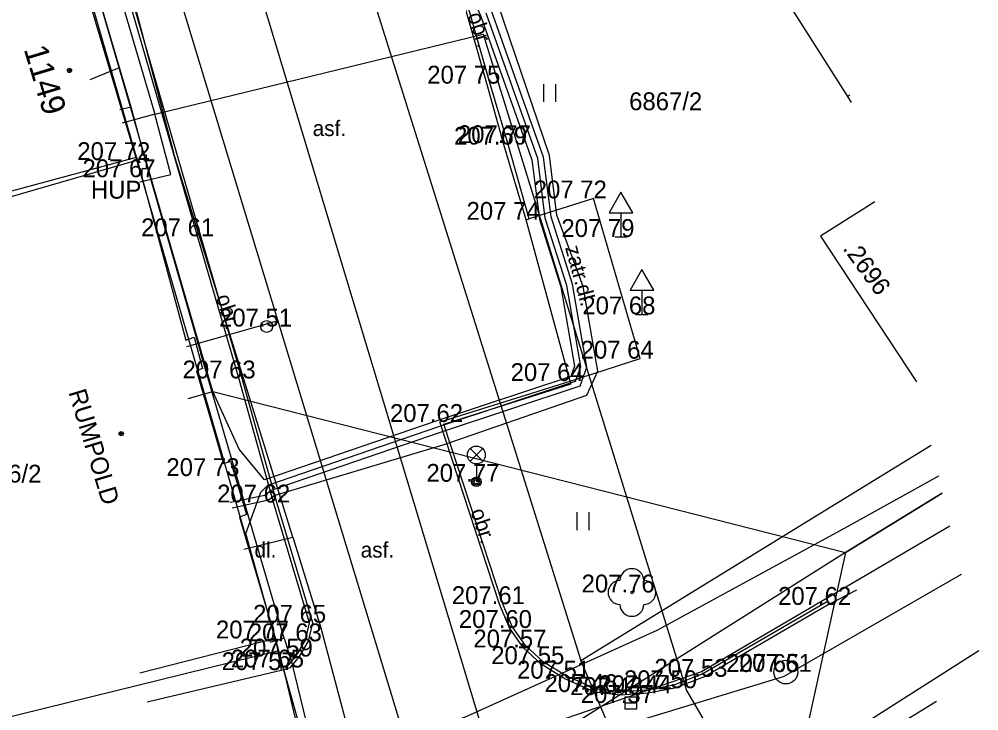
# Model space of a CAD drawing. Extents: x -524633 to -524336, y -1187893 to -1187683.
# Drawn here: x -524505.26 to -524464.98, y -1187849.14 to -1187820.09 of the extents above; entities that cross this region are included whole.
import ezdxf

# ---------------------------------------------------------------- set-up
doc = ezdxf.new("R2010")
doc.units = 0
for name, color, linetype in [('Hranice parcel', 7, 'Continuous'), ('Parcelní čísla', 7, 'Continuous'), ('Vrstva 1', 7, 'Continuous'), ('Vrstva 10', 7, 'Continuous'), ('Vrstva 11', 7, 'Continuous'), ('Vrstva 22', 7, 'Continuous'), ('Vrstva 24', 7, 'Continuous'), ('Vrstva 27', 7, 'Continuous'), ('Vrstva 28', 7, 'Continuous'), ('Vrstva 3', 7, 'Continuous'), ('Vrstva 33', 7, 'Continuous'), ('Vrstva 34', 7, 'Continuous'), ('Vrstva 36', 7, 'Continuous'), ('Vrstva 39', 7, 'Continuous'), ('Vrstva 4', 7, 'Continuous'), ('Vrstva 40', 7, 'Continuous'), ('Vrstva 41', 7, 'Continuous'), ('Vrstva 47', 7, 'Continuous'), ('Vrstva 5', 7, 'Continuous'), ('Vrstva 52', 7, 'Continuous'), ('Vrstva 53', 7, 'Continuous'), ('Vrstva 54', 7, 'Continuous'), ('Vrstva 55', 7, 'Continuous'), ('Vrstva 56', 7, 'Continuous'), ('Vrstva 58', 7, 'Continuous'), ('Vrstva 7', 7, 'Continuous')]:
    doc.layers.add(name, color=color, linetype=linetype)

msp = doc.modelspace()

# ---------------------------------------------------------------- linework, layer by layer
at = {"layer": 'Hranice parcel'}
for p, q in [((-524500.33, -1187825.89), (-524502.57, -1187818.16)), ((-524470.48, -1187823.34), (-524473.64, -1187818.37)), ((-524470.389, -1187823.283), (-524470.48, -1187823.34)), ((-524470.317, -1187823.593), (-524470.48, -1187823.34)), ((-524494.54, -1187845.97), (-524494.37, -1187846.6)), ((-524477.11, -1187857.62), (-524481.69, -1187847.02))]:
    msp.add_line(p, q, dxfattribs=at)
for points in [[(-524490.45, -1187819.04), (-524486.12, -1187832.88), (-524481.69, -1187847.02)], [(-524515.16, -1187829.92), (-524513.47, -1187829.44), (-524512.21, -1187829.1), (-524500.33, -1187825.89)], [(-524500.33, -1187825.89), (-524498.27, -1187833.57), (-524497.91, -1187833.45), (-524497.56, -1187834.77), (-524497.81, -1187834.86), (-524496.68, -1187838.75), (-524496.39, -1187838.65), (-524495.72, -1187840.9), (-524496.01, -1187841.01), (-524494.54, -1187845.97)], [(-524469.349, -1187827.764), (-524471.63, -1187829.2), (-524467.598, -1187835.318)], [(-524515.16, -1187829.92), (-524509.15, -1187850.24), (-524494.37, -1187846.6)], [(-524481.69, -1187847.02), (-524471.22, -1187840.59), (-524466.981, -1187837.979)], [(-524494.37, -1187846.6), (-524494.12, -1187847.57), (-524492.85, -1187852.95), (-524492.64, -1187853.18)]]:
    msp.add_lwpolyline(points, dxfattribs=at)
at = {"layer": 'Vrstva 1'}
for p, q in [((-524485.63, -1187822.8), (-524485.63, -1187822.8)), ((-524484.91, -1187825.36), (-524484.91, -1187825.36)), ((-524484.75, -1187825.3), (-524484.75, -1187825.3)), ((-524500.32, -1187826.01), (-524500.32, -1187826.01)), ((-524500.1, -1187826.73), (-524500.1, -1187826.73)), ((-524481.16, -1187827.62), (-524481.16, -1187827.62)), ((-524483.98, -1187828.52), (-524483.98, -1187828.52)), ((-524497.64, -1187829.21), (-524497.64, -1187829.21)), ((-524480, -1187829.24), (-524480, -1187829.24)), ((-524479.12, -1187832.49), (-524479.12, -1187832.49)), ((-524494.87, -1187833), (-524494.87, -1187833)), ((-524479.19, -1187834.35), (-524479.19, -1187834.35)), ((-524495.9, -1187835.18), (-524495.9, -1187835.18)), ((-524482.13, -1187835.29), (-524482.13, -1187835.29)), ((-524487.6, -1187837.01), (-524487.6, -1187837.01)), ((-524496.58, -1187839.28), (-524496.58, -1187839.28)), ((-524486.07, -1187839.52), (-524486.07, -1187839.52)), ((-524494.45, -1187840.39), (-524494.45, -1187840.39)), ((-524479.54, -1187844.17), (-524479.54, -1187844.17)), ((-524485.1, -1187844.66), (-524485.1, -1187844.66)), ((-524471.31, -1187844.69), (-524471.31, -1187844.69)), ((-524492.94, -1187845.44), (-524492.94, -1187845.44)), ((-524484.68, -1187845.66), (-524484.68, -1187845.66)), ((-524494.5, -1187846.1), (-524494.5, -1187846.1)), ((-524493.12, -1187846.22), (-524493.12, -1187846.22)), ((-524484.1, -1187846.48), (-524484.1, -1187846.48)), ((-524493.5, -1187846.86), (-524493.5, -1187846.86)), ((-524483.35, -1187847.18), (-524483.35, -1187847.18)), ((-524494.26, -1187847.43), (-524494.26, -1187847.43)), ((-524493.87, -1187847.32), (-524493.87, -1187847.32)), ((-524473.08, -1187847.51), (-524473.08, -1187847.51)), ((-524473.05, -1187847.5), (-524473.05, -1187847.5)), ((-524482.36, -1187847.79), (-524482.36, -1187847.79)), ((-524476.5, -1187847.71), (-524476.5, -1187847.71)), ((-524481.1, -1187848.35), (-524481.1, -1187848.35)), ((-524480.04, -1187848.48), (-524480.04, -1187848.48)), ((-524478.85, -1187848.4), (-524478.85, -1187848.4)), ((-524477.75, -1187848.19), (-524477.75, -1187848.19)), ((-524479.59, -1187848.81), (-524479.59, -1187848.81))]:
    msp.add_line(p, q, dxfattribs=at)
at = {"layer": 'Vrstva 10'}
for p, q in [((-524470.108, -1187844.07), (-524471.309, -1187844.69)), ((-524499.889, -1187848.761), (-524494.259, -1187847.43))]:
    msp.add_line(p, q, dxfattribs=at)
for points in [[(-524485.629, -1187822.8), (-524486.979, -1187818.07), (-524488.219, -1187813.67)], [(-524497.64, -1187829.21), (-524500.549, -1187819.15)], [(-524483.979, -1187828.52), (-524484.909, -1187825.36), (-524485.629, -1187822.8)], [(-524482.129, -1187835.29), (-524483.979, -1187828.52)], [(-524495.899, -1187835.18), (-524497.64, -1187829.21)], [(-524494.449, -1187840.39), (-524495.899, -1187835.18)], [(-524487.589, -1187837.01), (-524482.129, -1187835.29)], [(-524471.309, -1187844.69), (-524476.499, -1187847.71), (-524477.749, -1187848.19), (-524478.849, -1187848.4), (-524480.039, -1187848.48), (-524481.1, -1187848.35), (-524482.36, -1187847.79), (-524483.349, -1187847.18), (-524484.099, -1187846.48), (-524484.679, -1187845.66), (-524485.1, -1187844.66), (-524487.6, -1187837.01)], [(-524492.939, -1187845.44), (-524494.449, -1187840.39)], [(-524494.259, -1187847.43), (-524493.869, -1187847.32), (-524493.499, -1187846.86), (-524493.119, -1187846.22), (-524492.939, -1187845.44)], [(-524466.75, -1187848.751), (-524468.76, -1187849.98)]]:
    msp.add_lwpolyline(points, dxfattribs=at)
at = {"layer": 'Vrstva 11'}
for p, q in [((-524497.765, -1187829.246), (-524500.674, -1187819.186)), ((-524481.159, -1187827.62), (-524483.855, -1187828.48)), ((-524496.024, -1187835.216), (-524497.765, -1187829.246)), ((-524494.574, -1187840.426), (-524496.024, -1187835.216)), ((-524493.073, -1187845.444), (-524494.574, -1187840.426))]:
    msp.add_line(p, q, dxfattribs=at)
for points in [[(-524485.504, -1187822.764), (-524486.864, -1187818), (-524486.979, -1187818.07)], [(-524483.979, -1187828.52), (-524483.855, -1187828.48), (-524484.749, -1187825.3), (-524485.504, -1187822.764)], [(-524479.189, -1187834.35), (-524481.159, -1187827.62)], [(-524482.129, -1187835.29), (-524479.189, -1187834.35)], [(-524487.435, -1187837.098), (-524482.09, -1187835.414), (-524482.129, -1187835.29)], [(-524471.375, -1187844.578), (-524476.556, -1187847.592), (-524477.785, -1187848.064), (-524478.866, -1187848.271), (-524480.036, -1187848.349), (-524481.065, -1187848.223), (-524482.299, -1187847.675), (-524483.27, -1187847.076), (-524484.001, -1187846.394), (-524484.565, -1187845.597), (-524484.978, -1187844.615), (-524487.435, -1187837.098)], [(-524494.282, -1187847.301), (-524493.944, -1187847.206), (-524493.606, -1187846.786), (-524493.241, -1187846.171), (-524493.073, -1187845.444)]]:
    msp.add_lwpolyline(points, dxfattribs=at)
at = {"layer": 'Vrstva 22'}
msp.add_circle((-524479.54, -1187844.17), 0.05, dxfattribs=at)
for centre, start, end in [((-524479.54, -1187843.67), 0, 180), ((-524480.04, -1187844.17), 90, 270), ((-524479.04, -1187844.17), 270, 90), ((-524479.54, -1187844.67), 180, 0)]:
    msp.add_arc(centre, 0.5, start, end, dxfattribs=at)
at = {"layer": 'Vrstva 24'}
for p, q in [((-524500.099, -1187825.809), (-524500.099, -1187825.441)), ((-524499.916, -1187825.811), (-524500.099, -1187825.809)), ((-524499.916, -1187826.363), (-524499.916, -1187825.811)), ((-524500.099, -1187826.73), (-524500.099, -1187826.363)), ((-524500.099, -1187826.363), (-524499.916, -1187826.363))]:
    msp.add_line(p, q, dxfattribs=at)
at = {"layer": 'Vrstva 27'}
msp.add_line((-524479.84, -1187848.81), (-524479.34, -1187848.81), dxfattribs=at)
msp.add_lwpolyline([(-524479.84, -1187849.06), (-524479.34, -1187849.06), (-524479.34, -1187848.56), (-524479.84, -1187848.56)], close=True, dxfattribs=at)
msp.add_circle((-524473.08, -1187847.51), 0.5, dxfattribs=at)
at = {"layer": 'Vrstva 28'}
msp.add_circle((-524494.87, -1187833), 0.25, dxfattribs=at)
at = {"layer": 'Vrstva 33'}
for p, q in [((-524486.334, -1187838.66), (-524485.804, -1187838.13)), ((-524486.334, -1187838.13), (-524485.804, -1187838.66)), ((-524486.069, -1187838.77), (-524486.069, -1187839.52))]:
    msp.add_line(p, q, dxfattribs=at)
for centre, radius in [((-524486.069, -1187838.395), 0.375), ((-524486.069, -1187839.52), 0.2), ((-524486.069, -1187839.52), 0.145), ((-524486.069, -1187839.52), 0.0876)]:
    msp.add_circle(centre, radius, dxfattribs=at)
at = {"layer": 'Vrstva 34'}
for p, q in [((-524479.999, -1187828.224), (-524479.999, -1187829.24)), ((-524480.249, -1187829.24), (-524479.749, -1187829.24)), ((-524479.119, -1187831.474), (-524479.119, -1187832.49)), ((-524479.369, -1187832.49), (-524478.869, -1187832.49))]:
    msp.add_line(p, q, dxfattribs=at)
for points in [[(-524480.499, -1187828.224), (-524479.499, -1187828.224), (-524479.999, -1187827.356)], [(-524479.619, -1187831.474), (-524478.619, -1187831.474), (-524479.119, -1187830.606)]]:
    msp.add_lwpolyline(points, close=True, dxfattribs=at)
at = {"layer": 'Vrstva 36'}
for p, q in [((-524483.236, -1187823.568), (-524483.236, -1187822.818)), ((-524482.735, -1187823.568), (-524482.735, -1187822.818)), ((-524481.838, -1187841.548), (-524481.838, -1187840.798)), ((-524481.337, -1187841.548), (-524481.337, -1187840.798))]:
    msp.add_line(p, q, dxfattribs=at)
at = {"layer": 'Vrstva 39'}
for centre, radius in [((-524503.147, -1187822.243), 0.09), ((-524503.147, -1187822.243), 0.0398), ((-524500.973, -1187837.5), 0.09), ((-524500.973, -1187837.5), 0.0398)]:
    msp.add_circle(centre, radius, dxfattribs=at)
at = {"layer": 'Vrstva 5'}
for p, q in [((-524500.319, -1187826.01), (-524502.239, -1187819.58)), ((-524509.062, -1187828.548), (-524500.319, -1187826.01)), ((-524494.499, -1187846.1), (-524500.319, -1187826.01)), ((-524494.499, -1187846.1), (-524500.201, -1187847.552))]:
    msp.add_line(p, q, dxfattribs=at)
at = {"layer": 'Vrstva 52'}
for points in [[(-524496.398, -1187840.378), (-524494.948, -1187840.08), (-524494.688, -1187839.875), (-524487.612, -1187837.45), (-524481.715, -1187835.492), (-524481.43, -1187834.708), (-524482.034, -1187831.222), (-524482.934, -1187828.39), (-524483.247, -1187825.883), (-524485.431, -1187819.747), (-524488.09, -1187813.944), (-524489.77, -1187814.215), (-524492.275, -1187815.202), (-524493.527, -1187813.248), (-524494.448, -1187809.538), (-524497.926, -1187800.125), (-524501.727, -1187790.707), (-524504.173, -1187784.072), (-524504.862, -1187780.152), (-524505.655, -1187777.244), (-524505.315, -1187776.503)], [(-524486.634, -1187812.757), (-524487.014, -1187813.084), (-524487.375, -1187813.9), (-524488.263, -1187814.766), (-524485.893, -1187819.939), (-524483.735, -1187826.005), (-524483.424, -1187828.498), (-524482.522, -1187831.332), (-524481.946, -1187834.662), (-524482.103, -1187835.094), (-524487.772, -1187836.976), (-524494.962, -1187839.441), (-524496.019, -1187838.148), (-524497.136, -1187835.732)], [(-524496.323, -1187840.62), (-524494.794, -1187840.283), (-524494.551, -1187840.092), (-524487.422, -1187837.952), (-524481.428, -1187835.884), (-524480.97, -1187834.874), (-524481.585, -1187831.318), (-524482.69, -1187828.33), (-524483.003, -1187825.824), (-524485.394, -1187818.765), (-524487.797, -1187813.983), (-524487.557, -1187813.745), (-524487.237, -1187812.921), (-524486.827, -1187812.738)], [(-524490.8, -1187855.27), (-524491.509, -1187855.045), (-524491.879, -1187854.791), (-524492.603, -1187852.981), (-524495.751, -1187841.691), (-524495.113, -1187839.951), (-524494.825, -1187839.658), (-524487.692, -1187837.213), (-524481.909, -1187835.293), (-524481.688, -1187834.685), (-524482.278, -1187831.277), (-524483.179, -1187828.444), (-524483.491, -1187825.944), (-524485.662, -1187819.843)]]:
    msp.add_lwpolyline(points, dxfattribs=at)
at = {"layer": 'Vrstva 53'}
msp.add_line((-524501.03, -1187823.88), (-524500.57, -1187823.77), dxfattribs=at)
for points in [[(-524525.446, -1187746.167), (-524511.928, -1187773.746), (-524506.531, -1187798.067), (-524502.9, -1187810.999), (-524500.825, -1187817.931), (-524498.784, -1187825.686)], [(-524503.71, -1187812.98), (-524502.16, -1187818.34), (-524500.57, -1187823.77)], [(-524500.57, -1187823.77), (-524499.94, -1187826.11), (-524497.64, -1187834.14)], [(-524495.828, -1187842.35), (-524493.779, -1187841.853), (-524498.784, -1187825.686)], [(-524494.72, -1187846.26), (-524494.13, -1187846.09), (-524497.64, -1187834.14)], [(-524498.16, -1187836.027), (-524497.13, -1187835.73), (-524470.58, -1187842.49), (-524466.513, -1187839.999)], [(-524493.779, -1187841.853), (-524492.603, -1187845.66), (-524490.048, -1187855.237), (-524488.2, -1187858.565), (-524477.804, -1187853.476), (-524470.455, -1187850.093), (-524464.979, -1187846.613)], [(-524494.13, -1187846.09), (-524493.83, -1187847.08), (-524492.34, -1187853.18), (-524490.3, -1187859.77), (-524486.65, -1187864.92)]]:
    msp.add_lwpolyline(points, dxfattribs=at)
at = {"layer": 'Vrstva 54'}
for p, q in [((-524488.745, -1187851.342), (-524510.722, -1187778.991)), ((-524494.39, -1187832.756), (-524498.238, -1187833.847)), ((-524466.19, -1187841.39), (-524476.612, -1187847.502)), ((-524476.612, -1187847.502), (-524488.647, -1187851.626))]:
    msp.add_line(p, q, dxfattribs=at)
at = {"layer": 'Vrstva 55'}
for p, q in [((-524497.74, -1187810.36), (-524485.38, -1187851.41)), ((-524465.721, -1187843.413), (-524473.14, -1187847.68)), ((-524485.38, -1187851.41), (-524473.14, -1187847.68))]:
    msp.add_line(p, q, dxfattribs=at)
at = {"layer": 'Vrstva 56'}
msp.add_line((-524499.57, -1187824.08), (-524500.94, -1187824.46), dxfattribs=at)
for points in [[(-524504.89, -1187810.93), (-524503.54, -1187810.56), (-524499.57, -1187824.08)], [(-524499.57, -1187824.08), (-524485.78, -1187820.72), (-524477.25, -1187848.28), (-524474.27, -1187853.39), (-524473.29, -1187854.89)], [(-524500.19, -1187826.93), (-524498.89, -1187826.61), (-524499.57, -1187824.08)], [(-524466.678, -1187839.287), (-524470.48, -1187841.4), (-524478.49, -1187845.76), (-524486.54, -1187849.41), (-524494.18, -1187851.86)]]:
    msp.add_lwpolyline(points, dxfattribs=at)
at = {"layer": 'Vrstva 58'}
for points in [[(-524497.136, -1187835.732), (-524501.064, -1187822.132), (-524504.756, -1187809.419)], [(-524501.064, -1187822.132), (-524502.288, -1187822.635)], [(-524466.513, -1187839.999), (-524470.58, -1187842.49), (-524489.901, -1187854.702), (-524490.8, -1187855.27)], [(-524470.58, -1187842.49), (-524474.043, -1187858.306), (-524472.329, -1187857.318)]]:
    msp.add_lwpolyline(points, dxfattribs=at)
at = {"layer": 'Vrstva 7'}
msp.add_line((-524494.499, -1187846.1), (-524494.259, -1187847.43), dxfattribs=at)

# ---------------------------------------------------------------- texts
at = {"layer": 'Parcelní čísla'}
for s, p in [('6867/2', (-524479.656, -1187823.917)), ('.1006/2', (-524507.672, -1187839.555))]:
    msp.add_text(s, height=0.75, dxfattribs=at).set_placement(p)
msp.add_text('.2696', height=0.75, rotation=306, dxfattribs=at).set_placement((-524470.712, -1187829.728))
at = {"layer": 'Vrstva 3'}
for s, p in [('207 75 ', (-524488.13, -1187822.8)), ('207.69', (-524487.004, -1187825.36)), ('207 72 ', (-524502.82, -1187826.01)), ('207 61 ', (-524500.14, -1187829.21)), ('207 79 ', (-524482.5, -1187829.24)), ('207 68 ', (-524481.62, -1187832.49)), ('207.51', (-524496.87, -1187833)), ('207 63 ', (-524498.4, -1187835.18)), ('207 64 ', (-524484.63, -1187835.29)), ('207.62', (-524489.694, -1187837.01)), ('207.77', (-524488.164, -1187839.52)), ('207 62 ', (-524496.95, -1187840.39)), ('207.76', (-524481.651, -1187844.17)), ('207.62', (-524473.404, -1187844.69)), ('207 65 ', (-524495.44, -1187845.44)), ('207.57', (-524486.194, -1187846.48)), ('207 57 ', (-524496.76, -1187847.43)), ('207 65 ', (-524475.58, -1187847.51)), ('207.37', (-524481.684, -1187848.81))]:
    msp.add_text(s, height=0.75, dxfattribs=at).set_placement(p)
at = {"layer": 'Vrstva 4'}
for s, p in [('207.77', (-524486.844, -1187825.3)), ('207 67 ', (-524502.6, -1187826.73)), ('207 72 ', (-524483.66, -1187827.62)), ('207 74 ', (-524486.48, -1187828.52)), ('207 64 ', (-524481.69, -1187834.35)), ('207 73 ', (-524499.08, -1187839.28)), ('207.61', (-524487.1, -1187844.66)), ('207.60', (-524486.804, -1187845.66)), ('207 77 ', (-524497, -1187846.1)), ('207 63 ', (-524495.62, -1187846.22)), ('207 59 ', (-524496, -1187846.86)), ('207.55', (-524485.445, -1187847.18)), ('207 65 ', (-524496.37, -1187847.32)), ('207.61', (-524475.05, -1187847.5)), ('207.51', (-524484.36, -1187847.79)), ('207.53', (-524478.594, -1187847.71)), ('207.46', (-524483.211, -1187848.35)), ('207.44', (-524480.944, -1187848.4)), ('207.50', (-524479.874, -1187848.19)), ('207.43', (-524482.134, -1187848.48))]:
    msp.add_text(s, height=0.75, dxfattribs=at).set_placement(p)
at = {"layer": 'Vrstva 40'}
for s, rotation, p in [('obr.', 288.0973, (-524486.447, -1187819.921)), ('zatr.dl.', 285.2838, (-524482.349, -1187829.685)), ('obr.', 287.4555, (-524497.004, -1187831.758)), ('obr.', 288.0973, (-524486.32, -1187840.755))]:
    msp.add_text(s, height=0.65, rotation=rotation, dxfattribs=at).set_placement(p)
for s, p in [('asf.', (-524492.938, -1187825.002)), ('dl.', (-524495.381, -1187842.703)), ('asf.', (-524490.924, -1187842.703))]:
    msp.add_text(s, height=0.65, dxfattribs=at).set_placement(p)
at = {"layer": 'Vrstva 41'}
msp.add_text('HUP', height=0.75, dxfattribs=at).set_placement((-524502.246, -1187827.63))
msp.add_text('RUMPOLD', height=0.75, rotation=286.8364, dxfattribs=at).set_placement((-524503.198, -1187835.757))
at = {"layer": 'Vrstva 47'}
msp.add_text('1149', height=1, rotation=286.8364, dxfattribs=at).set_placement((-524505.073, -1187821.352))

doc.saveas('drawing.dxf')
